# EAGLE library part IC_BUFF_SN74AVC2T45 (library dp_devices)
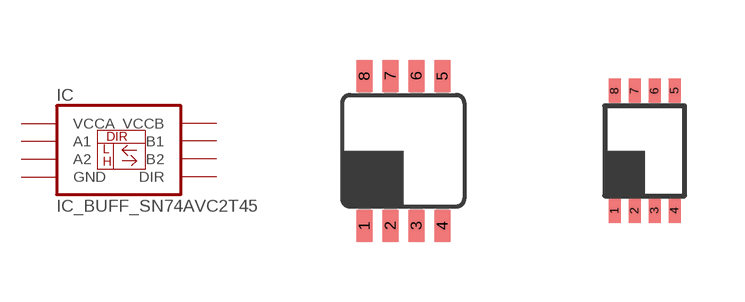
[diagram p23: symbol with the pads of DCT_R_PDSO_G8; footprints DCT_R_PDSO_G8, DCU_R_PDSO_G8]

Designator prefix IC

## IC_BUFF_SN74AVC2T45DCT  [DCT_R_PDSO_G8]
1  VCCA
2  A1
3  A2
4  GND
5  DIR
6  B2
7  B1
8  VCCB

## IC_BUFF_SN74AVC2T45DCU  [DCU_R_PDSO_G8]
Pads as for DCT_R_PDSO_G8

## Footprint DCT_R_PDSO_G8 (pad centres in mm)
smd 0.4 x 0.8: 1 -0.975,-1.875; 2 -0.325,-1.875; 3 0.325,-1.875; 4 0.975,-1.875; 5 0.975,1.875; 6 0.325,1.875; 7 -0.325,1.875; 8 -0.975,1.875

## Footprint DCU_R_PDSO_G8 (pad centres in mm)
smd 0.3 x 0.6: 1 -0.75,-1.5; 2 -0.25,-1.5; 3 0.25,-1.5; 4 0.75,-1.5; 5 0.75,1.5; 6 0.25,1.5; 7 -0.25,1.5; 8 -0.75,1.5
